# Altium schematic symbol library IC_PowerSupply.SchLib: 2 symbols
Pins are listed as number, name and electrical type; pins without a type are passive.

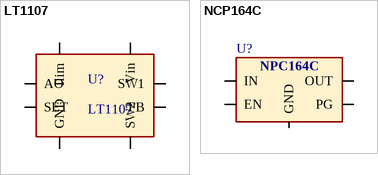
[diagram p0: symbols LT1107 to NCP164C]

## LT1107
designator U?
Micropower / DC/DC Converter / Adjustable and Fixed 5V, 12V; Manufacturer: Linear technology
footprint SOIC127P600X175-8N (SOIC, 8-Leads, Body 4.90x3.90mm, Pitch 1.27mm, IPC Medium Density)
pins: 1 Ilim "Connect this pin to VIN for normal use. Where", 2 Vin (power) "Input Supply Voltage.", 3 SW1 (power) "Collector of Power Transistor. For step-up", 4 SW2 (power) "Emitter of Power Transistor. For step-up", 5 GND, 6 AO "Auxiliary Gain Block (GB) Output. Open collector,", 7 SET "GB Input. GB is an op amp with positive input", 8 FB "On the LT1107 (adjustable), this pin"

## NCP164C
designator U?  (value not drawn)
LDO Regulator, 300mA, / Low Dropout Voltage, Ultra Low Noise, High PSRR with Power Good; Manufacturer: On Semiconductor; Mfr Part Num.: NCP164CSN330T1G; Input Voltage: 1.6V~5V; Current: 300mA; Output Voltage: 3.3V
footprint NCP164C_TSOP-5 (TSOP, 6-Leads, Body 3.00x1.50mm, Pitch 0.95mm, IPC Medium Density)
pins: 1 IN (power), 2 GND (power), 3 EN (power), 4 PG (power), 5 OUT (power)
